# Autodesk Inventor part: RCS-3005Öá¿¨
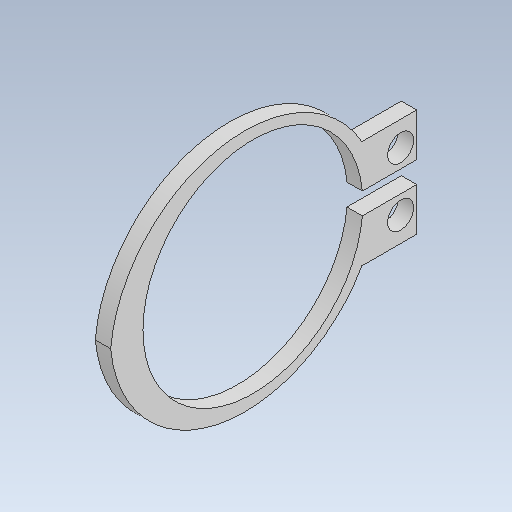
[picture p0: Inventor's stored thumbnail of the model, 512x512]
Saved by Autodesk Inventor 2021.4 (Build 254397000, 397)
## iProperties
Created: 2019-12
Part Number: RCS-3005Öá¿¨
Material: Ogólny
Document SubType Name: Modeling
Designer: user
Density: 1 g/cm^3
Appearance: Domyślna
Author: user
Revision Number: ÈÎºÎ
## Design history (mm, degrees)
feature "2"
node "Bryła1"
